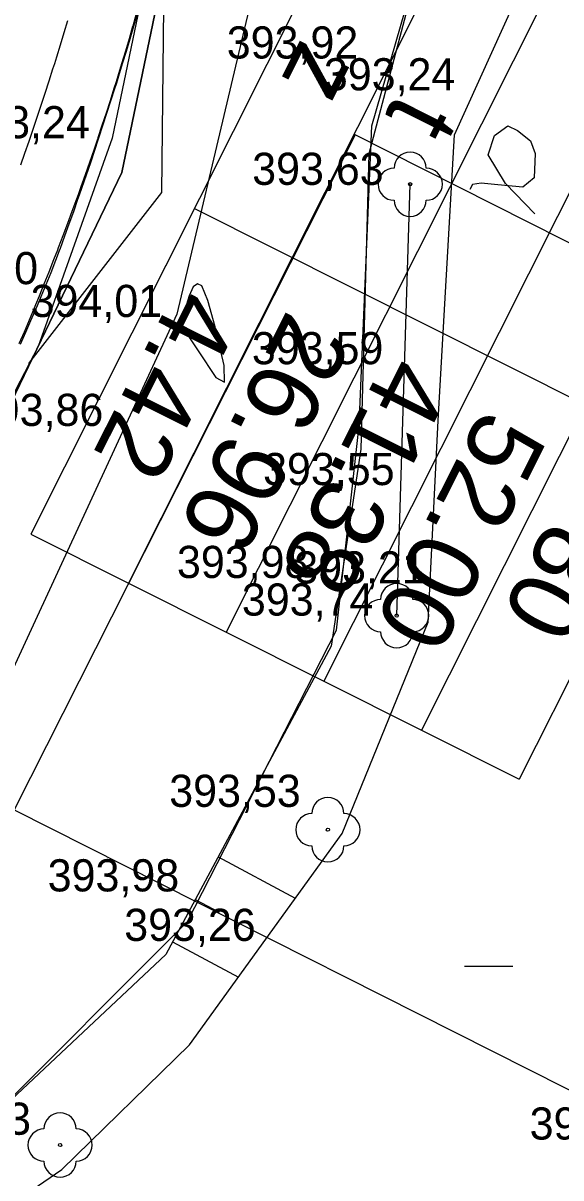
# Model space of a CAD drawing. Extents: x -574342 to -507939, y -1144044 to -1123894.
# Drawn here: x -508508.86 to -508492.13, y -1143152.64 to -1143116.72 of the extents above; entities that cross this region are included whole.
import ezdxf

# ---------------------------------------------------------------- set-up
doc = ezdxf.new("R2010")
doc.units = 0
for name, color, linetype in [('01_PARCELY_NAVRH_PC', 7, 'Continuous'), ('01_PARCELY_NAVRH_VHO', 7, 'Continuous'), ('01_PARCELY_NAVRH_ŽP', 7, 'Continuous'), ('1000', 7, 'Continuous'), ('21', 7, 'Continuous'), ('37', 7, 'Continuous'), ('43', 7, 'Continuous'), ('51', 7, 'Continuous'), ('54', 7, 'Continuous'), ('55', 7, 'Continuous'), ('60', 7, 'Continuous'), ('61', 7, 'Continuous'), ('Level 255', 7, 'Continuous'), ('SO 101_popis oblouku', 7, 'Continuous'), ('tab', 7, 'Continuous'), ('VRST VEDL', 7, 'Continuous')]:
    doc.layers.add(name, color=color, linetype=linetype)

msp = doc.modelspace()

# ---------------------------------------------------------------- linework, layer by layer
msp.add_lwpolyline([(-508498.535, -1143120.193), (-508509.135, -1143141.189), (-508489.699, -1143151.002), (-508479.099, -1143130.006)], close=True)
at = {"layer": '01_PARCELY_NAVRH_PC'}
msp.add_lwpolyline([(-508539.86, -1143167.27), (-508535.17, -1143170.73), (-508529.25, -1143158.67), (-508513.07, -1143136.47), (-508505.79, -1143121.37), (-508501.93, -1143102.81), (-508501.63, -1143092.13), (-508497.53, -1143088.05), (-508492.06, -1143088.51), (-508489.36, -1143093.44), (-508498.08, -1143065.7), (-508506.03, -1143042.25), (-508507.09, -1143063.68), (-508507.1, -1143101.54), (-508510.16, -1143116.01), (-508515.95, -1143130.65), (-508519.02, -1143135.54), (-508530.41, -1143150.9), (-508533.66, -1143155.6)], close=True, dxfattribs=at)
msp.add_lwpolyline([(-508539.86, -1143167.27), (-508535.17, -1143170.73), (-508529.25, -1143158.67), (-508513.07, -1143136.47), (-508505.79, -1143121.37), (-508501.93, -1143102.81), (-508501.63, -1143092.13), (-508497.53, -1143088.05), (-508492.06, -1143088.51), (-508489.36, -1143093.44), (-508498.08, -1143065.7), (-508506.03, -1143042.25), (-508507.09, -1143063.68), (-508507.1, -1143101.54), (-508510.16, -1143116.01), (-508515.95, -1143130.65), (-508519.02, -1143135.54), (-508530.41, -1143150.9), (-508533.66, -1143155.6)], close=True, dxfattribs=at)
at = {"layer": '01_PARCELY_NAVRH_VHO'}
msp.add_lwpolyline([(-508461.87, -1143244.49), (-508467.98, -1143243.62), (-508478.66, -1143222.38), (-508487.9, -1143213.8), (-508496.38, -1143198.1), (-508504.26, -1143191.1), (-508516.39, -1143188), (-508530.07, -1143174.68), (-508525.32, -1143175.64), (-508523.79, -1143164.91), (-508521.99, -1143159.7), (-508510.09, -1143151.01), (-508503.75, -1143144.67), (-508499.11, -1143135.6), (-508498.41, -1143129.24), (-508498.01, -1143119.91), (-508496.68, -1143115.27)], dxfattribs=at)
at = {"layer": '01_PARCELY_NAVRH_ŽP'}
msp.add_lwpolyline([(-508523.79, -1143164.91), (-508521.99, -1143159.7), (-508510.09, -1143151.01), (-508503.75, -1143144.67), (-508499.11, -1143135.6), (-508498.41, -1143129.24), (-508498.01, -1143119.91), (-508496.68, -1143115.27), (-508492.61, -1143111.73), (-508487.01, -1143113.01), (-508489.36, -1143093.44), (-508492.06, -1143088.51), (-508497.53, -1143088.05), (-508501.63, -1143092.13), (-508501.93, -1143102.81), (-508505.79, -1143121.37), (-508513.07, -1143136.47), (-508529.25, -1143158.67), (-508535.17, -1143170.73), (-508530.07, -1143174.68), (-508525.32, -1143175.64)], close=True, dxfattribs=at)
at = {"layer": '1000'}
for points in [[(-508505.341, -1143116.43), (-508505.451, -1143116.815), (-508505.452, -1143116.819), (-508505.565, -1143117.207), (-508505.679, -1143117.594), (-508505.795, -1143117.981), (-508505.914, -1143118.367), (-508505.979, -1143118.576), (-508506.034, -1143118.753), (-508506.156, -1143119.138), (-508506.28, -1143119.522), (-508506.406, -1143119.906), (-508506.533, -1143120.289), (-508506.545, -1143120.324), (-508506.663, -1143120.672), (-508506.794, -1143121.054), (-508506.928, -1143121.435), (-508507.063, -1143121.816), (-508507.151, -1143122.06), (-508507.2, -1143122.195), (-508507.339, -1143122.575), (-508507.48, -1143122.953), (-508507.623, -1143123.331), (-508507.767, -1143123.708), (-508507.795, -1143123.781), (-508507.914, -1143124.085), (-508508.062, -1143124.461), (-508508.212, -1143124.836), (-508508.364, -1143125.21), (-508508.478, -1143125.487), (-508508.518, -1143125.583), (-508508.674, -1143125.956), (-508508.831, -1143126.328), (-508508.991, -1143126.699)], [(-508505.315, -1143116.437), (-508505.427, -1143116.822), (-508505.428, -1143116.826), (-508505.542, -1143117.213), (-508505.657, -1143117.6), (-508505.775, -1143117.987), (-508505.894, -1143118.373), (-508505.959, -1143118.582), (-508506.015, -1143118.759), (-508506.137, -1143119.144), (-508506.261, -1143119.528), (-508506.387, -1143119.912), (-508506.514, -1143120.296), (-508506.525, -1143120.331), (-508506.64, -1143120.679), (-508506.768, -1143121.063), (-508506.898, -1143121.445), (-508507.03, -1143121.828), (-508507.115, -1143122.073), (-508507.163, -1143122.209), (-508507.297, -1143122.59), (-508507.434, -1143122.971), (-508507.572, -1143123.351), (-508507.712, -1143123.73), (-508507.739, -1143123.803), (-508507.853, -1143124.108), (-508508.002, -1143124.484), (-508508.155, -1143124.859), (-508508.31, -1143125.232), (-508508.426, -1143125.509), (-508508.467, -1143125.604), (-508508.625, -1143125.976), (-508508.786, -1143126.347), (-508508.947, -1143126.718)]]:
    msp.add_lwpolyline(points, dxfattribs=at)
at = {"layer": '21'}
msp.add_lwpolyline([(-508507.484, -1143116.645), (-508507.596, -1143117.023), (-508507.709, -1143117.4), (-508507.825, -1143117.777), (-508507.888, -1143117.981), (-508507.942, -1143118.153), (-508508.061, -1143118.529), (-508508.182, -1143118.904), (-508508.305, -1143119.278), (-508508.429, -1143119.652), (-508508.441, -1143119.686), (-508508.556, -1143120.025), (-508508.684, -1143120.398), (-508508.814, -1143120.77), (-508508.946, -1143121.141)], dxfattribs=at)
at = {"layer": '37'}
for points in [[(-508498.68, -1143059.63), (-508500.25, -1143055.07), (-508501.74, -1143064.81), (-508502.5, -1143084.28), (-508503.02, -1143105.54), (-508506.09, -1143120.3), (-508508.39, -1143126.78)], [(-508498.68, -1143059.63), (-508500.25, -1143055.07), (-508501.74, -1143064.81), (-508502.5, -1143084.28), (-508503.02, -1143105.54), (-508506.09, -1143120.3), (-508508.39, -1143126.78)], [(-508508.39, -1143126.78), (-508512.62, -1143134.91), (-508529.52, -1143158.24), (-508537.33, -1143172.61), (-508540.68, -1143183.59)], [(-508508.39, -1143126.78), (-508512.62, -1143134.91), (-508529.52, -1143158.24), (-508537.33, -1143172.61), (-508540.68, -1143183.59)]]:
    msp.add_lwpolyline(points, dxfattribs=at)
at = {"layer": '43'}
msp.add_line((-508495.131, -1143146.057), (-508493.631, -1143146.057), dxfattribs=at)
at = {"layer": '51'}
msp.add_lwpolyline([(-508520.2, -1143160.98), (-508507.66, -1143152.38), (-508503.68, -1143148.5), (-508498.94, -1143141.93), (-508496.26, -1143135.35), (-508495.95, -1143129.08), (-508495.44, -1143120.19), (-508493.12, -1143115.06), (-508490.39, -1143115.19), (-508486.94, -1143118.54), (-508484.73, -1143123.98), (-508484.03, -1143128.35), (-508482.47, -1143135.96), (-508481.24, -1143143.89), (-508483.67, -1143147.96), (-508487.25, -1143151.23), (-508497.6, -1143155.8), (-508504.12, -1143160.81), (-508512.14, -1143168.95), (-508515.5, -1143169.45), (-508518.57, -1143168.12), (-508521.82, -1143163.95)], close=True, dxfattribs=at)
msp.add_lwpolyline([(-508520.2, -1143160.98), (-508507.66, -1143152.38), (-508503.68, -1143148.5), (-508498.94, -1143141.93), (-508496.26, -1143135.35), (-508495.95, -1143129.08), (-508495.44, -1143120.19), (-508493.12, -1143115.06), (-508490.39, -1143115.19), (-508486.94, -1143118.54), (-508484.73, -1143123.98), (-508484.03, -1143128.35), (-508482.47, -1143135.96), (-508481.24, -1143143.89), (-508483.67, -1143147.96), (-508487.25, -1143151.23), (-508497.6, -1143155.8), (-508504.12, -1143160.81), (-508512.14, -1143168.95), (-508515.5, -1143169.45), (-508518.57, -1143168.12), (-508521.82, -1143163.95)], close=True, dxfattribs=at)
at = {"layer": '54'}
for centre in [(-508496.82, -1143121.73), (-508497.24, -1143135.15), (-508499.38, -1143141.81), (-508507.71, -1143151.62)]:
    msp.add_circle(centre, 0.05, dxfattribs=at)
for centre, start, end in [((-508496.82, -1143121.23), 0, 180), ((-508497.32, -1143121.73), 90, 270), ((-508496.32, -1143121.73), 270, 90), ((-508496.82, -1143122.23), 180, 0), ((-508497.24, -1143134.65), 0, 180), ((-508497.74, -1143135.15), 90, 270), ((-508496.74, -1143135.15), 270, 90), ((-508497.24, -1143135.65), 180, 0), ((-508499.38, -1143141.31), 0, 180), ((-508499.88, -1143141.81), 90, 270), ((-508498.88, -1143141.81), 270, 90), ((-508499.38, -1143142.31), 180, 0), ((-508507.71, -1143151.12), 0, 180), ((-508508.21, -1143151.62), 90, 270), ((-508507.21, -1143151.62), 270, 90), ((-508507.71, -1143152.12), 180, 0)]:
    msp.add_arc(centre, 0.5, start, end, dxfattribs=at)
at = {"layer": '55'}
msp.add_line((-508497.24, -1143135.15), (-508496.82, -1143121.73), dxfattribs=at)
msp.add_line((-508497.24, -1143135.15), (-508496.82, -1143121.73), dxfattribs=at)
msp.add_lwpolyline([(-508498.88, -1143086.48), (-508499.14, -1143104.9), (-508504.08, -1143125.77), (-508509.69, -1143137.89), (-508528.17, -1143161.51)], dxfattribs=at)
msp.add_lwpolyline([(-508498.88, -1143086.48), (-508499.14, -1143104.9), (-508504.08, -1143125.77), (-508509.69, -1143137.89), (-508528.17, -1143161.51)], dxfattribs=at)
at = {"layer": '60'}
msp.add_lwpolyline([(-508496.69, -1143115.41), (-508498.11, -1143120.78), (-508498.36, -1143129.97), (-508499.28, -1143136.1), (-508504.42, -1143145.69), (-508510.09, -1143151.01), (-508522.36, -1143160.17), (-508523.76, -1143165.4), (-508522.03, -1143168.68), (-508525.16, -1143176.55)], dxfattribs=at)
msp.add_lwpolyline([(-508496.69, -1143115.41), (-508498.11, -1143120.78), (-508498.36, -1143129.97), (-508499.28, -1143136.1), (-508504.42, -1143145.69), (-508510.09, -1143151.01), (-508522.36, -1143160.17), (-508523.76, -1143165.4), (-508522.03, -1143168.68), (-508525.16, -1143176.55)], dxfattribs=at)
at = {"layer": '61'}
for p, q in [((-508502.794, -1143142.656), (-508500.393, -1143143.943)), ((-508502.794, -1143142.656), (-508500.393, -1143143.943)), ((-508503.503, -1143143.978), (-508502.762, -1143144.375)), ((-508503.503, -1143143.978), (-508502.762, -1143144.375)), ((-508504.211, -1143145.3), (-508502.163, -1143146.398)), ((-508504.211, -1143145.3), (-508502.163, -1143146.398))]:
    msp.add_line(p, q, dxfattribs=at)
at = {"layer": 'SO 101_popis oblouku'}
for p, q in [((-508498.446, -1143112.358), (-508508.62, -1143132.613)), ((-508495.408, -1143113.884), (-508505.581, -1143134.139)), ((-508492.37, -1143115.41), (-508502.543, -1143135.665)), ((-508489.331, -1143116.936), (-508499.505, -1143137.191)), ((-508486.293, -1143118.462), (-508496.466, -1143138.717)), ((-508483.255, -1143119.988), (-508493.428, -1143140.243)), ((-508503.533, -1143122.486), (-508488.341, -1143130.115)), ((-508508.62, -1143132.613), (-508493.428, -1143140.243))]:
    msp.add_line(p, q, dxfattribs=at)
msp.add_lwpolyline([(-508492.938, -1143122.653), (-508493.854, -1143121.705), (-508494.393, -1143120.82), (-508494.198, -1143120.217), (-508493.783, -1143119.916), (-508493.482, -1143120.06), (-508493.075, -1143120.376), (-508492.932, -1143120.779), (-508492.963, -1143121.536), (-508493.318, -1143121.817), (-508494.097, -1143121.754), (-508494.614, -1143121.702), (-508494.883, -1143121.734), (-508494.964, -1143121.897)], dxfattribs=at)
at = {"layer": 'tab'}
msp.add_lwpolyline([(-508504.486, -1143115.252), (-508504.559, -1143121.991), (-508508.695, -1143127.311)], dxfattribs=at)
at = {"layer": 'VRST VEDL'}
msp.add_lwpolyline([(-508503.962, -1143126.086), (-508502.87, -1143127.74), (-508502.599, -1143127.891), (-508502.603, -1143127.367), (-508502.883, -1143126.167), (-508503.114, -1143125.343), (-508503.297, -1143124.896), (-508503.433, -1143124.825), (-508503.567, -1143124.926), (-508503.699, -1143125.198)], close=True, dxfattribs=at)

# ---------------------------------------------------------------- texts
at = {"layer": 'Level 255'}
for s, p in [('393,92', (-508502.525, -1143117.82)), ('393,24', (-508499.505, -1143118.81)), ('393,24', (-508510.875, -1143120.3)), ('393,63', (-508501.735, -1143121.75)), ('393,20', (-508512.485, -1143124.84)), ('394,01', (-508508.625, -1143125.86)), ('393,59', (-508501.745, -1143127.33)), ('393,86', (-508510.455, -1143129.25)), ('393,55', (-508501.395, -1143131.09)), ('393,98', (-508504.075, -1143133.98)), ('393,21', (-508500.425, -1143134.15)), ('393,74', (-508502.055, -1143135.15)), ('393,53', (-508504.315, -1143141.1)), ('393,98', (-508508.095, -1143143.73)), ('393,26', (-508505.715, -1143145.27)), ('393,63', (-508512.705, -1143151.3)), ('393,16', (-508493.105, -1143151.45))]:
    msp.add_text(s, height=1, dxfattribs=at).set_placement(p)
at = {"layer": 'SO 101_popis oblouku'}
for s, height, p in [('z', 2.267, (-508500.197, -1143117.155)), ('t', 2.267, (-508497.232, -1143118.826)), ('4.42', 2.2667, (-508504.067, -1143124.859)), ('26.96', 2.2667, (-508500.628, -1143125.589)), ('41.38', 2.2667, (-508497.509, -1143126.953)), ('52.00', 2.2667, (-508494.552, -1143128.641)), ('80', 2.2667, (-508492.489, -1143132.109))]:
    msp.add_text(s, height=height, rotation=243.3272, dxfattribs=at).set_placement(p)

doc.saveas('drawing.dxf')
